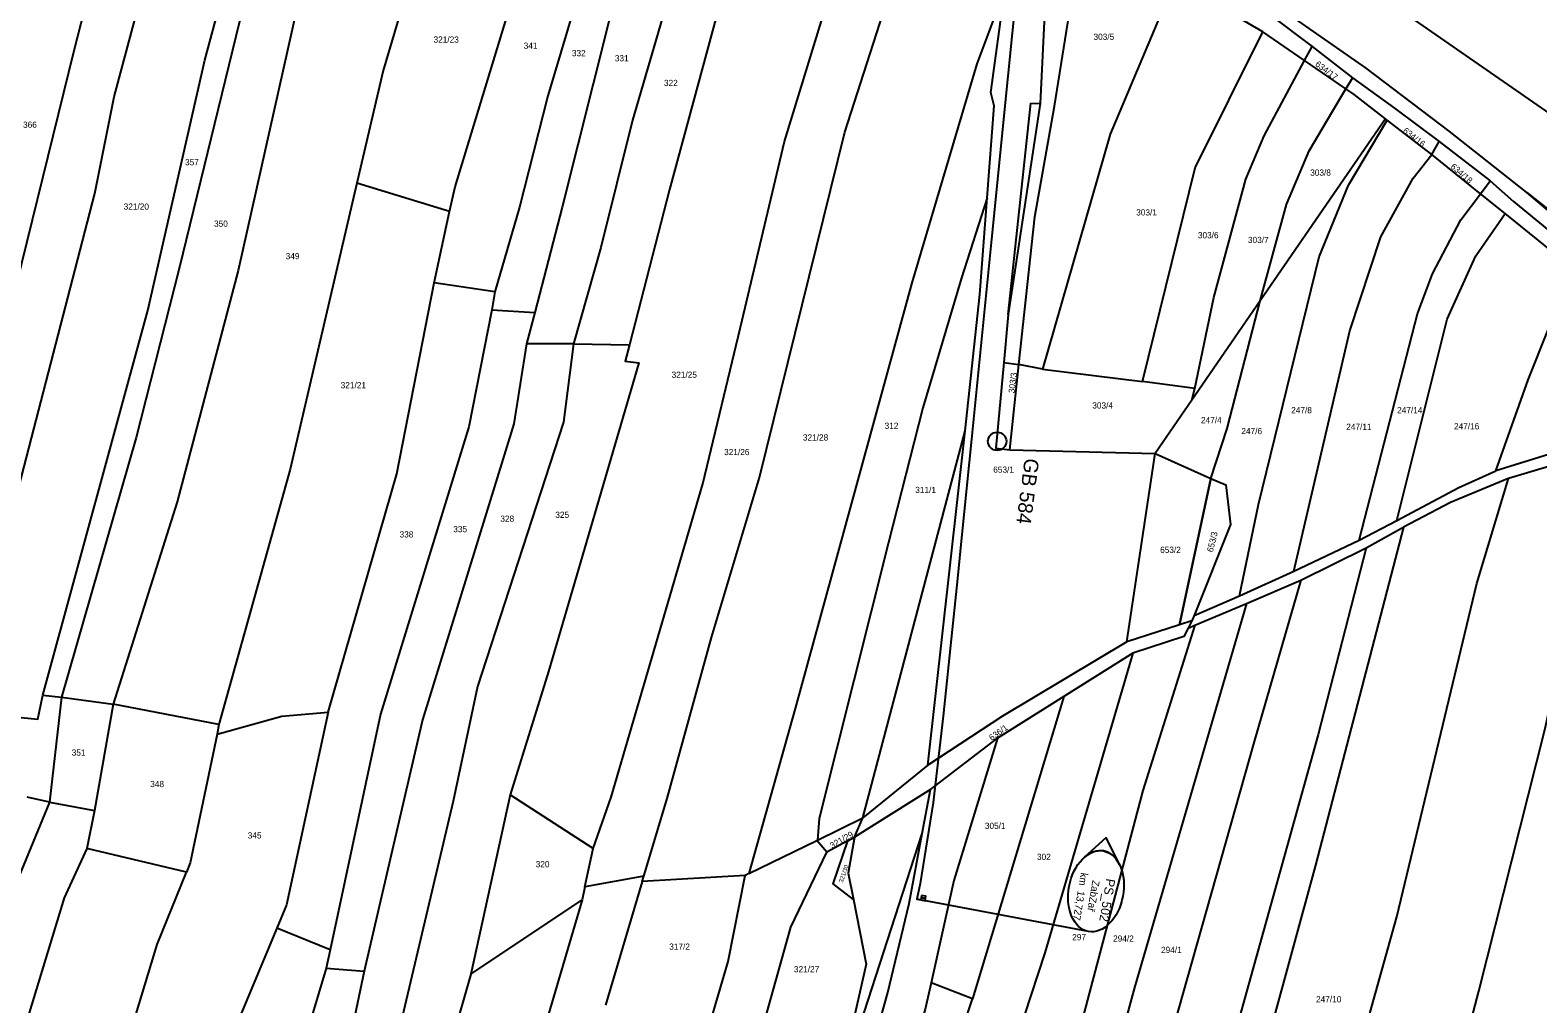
# Model space of a CAD drawing. Extents: x -746176 to -739709, y -1128407 to -1124482.
# Drawn here: x -743602.7 to -743188.7, y -1127823.5 to -1127556.1 of the extents above; entities that cross this region are included whole.
import ezdxf

# ---------------------------------------------------------------- set-up
doc = ezdxf.new("R2010")
doc.units = 0
for name, color, linetype in [('_Násyp', 7, 'Continuous'), ('_Zabezpečovací zařízení', 7, 'Continuous'), ('_Zabezpečovací zařízení_trasa', 7, 'Continuous'), ('bublina_růžová_230_čára_tenká', 7, 'Continuous'), ('bublina_růžová_230_čára_tučná', 7, 'Continuous'), ('Hranice parcel', 7, 'Continuous'), ('Parcelní čísla', 7, 'Continuous'), ('Vnitřní kresba', 7, 'Continuous'), ('Vrstva 53', 7, 'Continuous'), ('ŽBP', 7, 'Continuous')]:
    doc.layers.add(name, color=color, linetype=linetype)

msp = doc.modelspace()

# ---------------------------------------------------------------- linework, layer by layer
at = {"layer": '_Zabezpečovací zařízení'}
for p, q in [((-743357.94, -1127793.74), (-743358.15, -1127794.97)), ((-743358.15, -1127794.97), (-743356.92, -1127795.19)), ((-743356.81, -1127794.57), (-743358.04, -1127794.36)), ((-743356.71, -1127793.96), (-743357.94, -1127793.74)), ((-743356.92, -1127795.19), (-743356.71, -1127793.96))]:
    msp.add_line(p, q, dxfattribs=at)
msp.add_lwpolyline([(-743357.94, -1127793.74), (-743358.04, -1127794.36), (-743356.81, -1127794.57), (-743356.71, -1127793.96), (-743357.94, -1127793.74)], dxfattribs=at)
at = {"layer": '_Zabezpečovací zařízení_trasa'}
msp.add_lwpolyline([(-743301.12, -1127329.13), (-743306.79, -1127349.51), (-743311.54, -1127370.06), (-743315.69, -1127392.87), (-743318.79, -1127415.84), (-743321.57, -1127442.6), (-743324.27, -1127469.35), (-743329.51, -1127521.46), (-743334.23, -1127568.82), (-743338.71, -1127613.56), (-743341.47, -1127641), (-743342.85, -1127654.73), (-743344.22, -1127668.45), (-743346.84, -1127694.61), (-743348.17, -1127707.68), (-743349.5, -1127720.75), (-743351.96, -1127744.53), (-743354.76, -1127768.22), (-743358.32, -1127790.48), (-743359.2, -1127794.79), (-743358.15, -1127794.97)], dxfattribs=at)
at = {"layer": 'bublina_růžová_230_čára_tenká'}
msp.add_line((-743312.1, -1127803.66), (-743359.2, -1127794.79), dxfattribs=at)
at = {"layer": 'bublina_růžová_230_čára_tučná'}
for p, q in [((-743307.25, -1127777.86), (-743313.36, -1127783.41)), ((-743307.25, -1127777.86), (-743313.36, -1127783.41)), ((-743303.57, -1127785.25), (-743307.25, -1127777.86)), ((-743303.57, -1127785.25), (-743307.25, -1127777.86))]:
    msp.add_line(p, q, dxfattribs=at)
msp.add_ellipse((-743310.02, -1127792.6), major_axis=(-2.08, -11.06), ratio=0.666667, dxfattribs=at)
msp.add_ellipse((-743310.02, -1127792.6), major_axis=(2.08, 11.06), ratio=0.666473, start_param=5.557317, end_param=7.009053, dxfattribs=at)
at = {"layer": 'Hranice parcel'}
for p, q in [((-743264.18, -1127556.62), (-743288.35, -1127542.49)), ((-743252.73, -1127564.48), (-743264.18, -1127556.62)), ((-743252.73, -1127564.48), (-743250.66, -1127560.62)), ((-743250.66, -1127560.62), (-743239.62, -1127569.19)), ((-743241.42, -1127572.24), (-743252.73, -1127564.48)), ((-743239.62, -1127569.19), (-743241.42, -1127572.24)), ((-743230.52, -1127580.51), (-743264.95, -1127630.5)), ((-743230.04, -1127580.88), (-743230.52, -1127580.51)), ((-743217.78, -1127590.26), (-743230.04, -1127580.88)), ((-743217.78, -1127590.26), (-743215.78, -1127586.74)), ((-743204.41, -1127601.05), (-743217.78, -1127590.26)), ((-743215.78, -1127586.74), (-743201.77, -1127597.55)), ((-743487.51, -1127605.98), (-743512.98, -1127598.18)), ((-743204.41, -1127601.05), (-743201.77, -1127597.55)), ((-743197.68, -1127606.48), (-743204.41, -1127601.05)), ((-743491.75, -1127625.57), (-743487.51, -1127605.98)), ((-743475.06, -1127627.97), (-743491.75, -1127625.57)), ((-743475.06, -1127627.97), (-743475.93, -1127632.96)), ((-743264.95, -1127630.5), (-743283.69, -1127657.72)), ((-743475.93, -1127632.96), (-743464.14, -1127633.66)), ((-743464.14, -1127633.66), (-743466.39, -1127642.3)), ((-743453.46, -1127642.28), (-743466.39, -1127642.3)), ((-743453.46, -1127642.28), (-743438.1, -1127642.54)), ((-743335.37, -1127647.41), (-743331.17, -1127647.95)), ((-743333.67, -1127671.36), (-743331.17, -1127647.95)), ((-743324.73, -1127649.24), (-743331.17, -1127647.95)), ((-743324.73, -1127649.24), (-743297.22, -1127652.59)), ((-743282.86, -1127654.54), (-743297.22, -1127652.59)), ((-743283.69, -1127657.72), (-743282.86, -1127654.54)), ((-743283.69, -1127657.72), (-743293.8, -1127672.4)), ((-743333.67, -1127671.36), (-743293.8, -1127672.4)), ((-743301.55, -1127724.14), (-743293.8, -1127672.4)), ((-743293.8, -1127672.4), (-743278.45, -1127679.23)), ((-743165.44, -1127669.87), (-743196.8, -1127679.29)), ((-743287.1, -1127719.44), (-743278.45, -1127679.23)), ((-743237.76, -1127696.22), (-743227.38, -1127690.77)), ((-743255.66, -1127704.74), (-743237.76, -1127696.22)), ((-743253.81, -1127707.15), (-743235.82, -1127698.28)), ((-743270.64, -1127711.51), (-743255.66, -1127704.74)), ((-743268.66, -1127713.55), (-743253.81, -1127707.15)), ((-743283.11, -1127716.84), (-743270.64, -1127711.51)), ((-743282.88, -1127719.56), (-743268.66, -1127713.55)), ((-743283.71, -1127718.34), (-743287.1, -1127719.44)), ((-743283.71, -1127718.34), (-743284.74, -1127720.35)), ((-743283.11, -1127716.84), (-743283.71, -1127718.34)), ((-743287.1, -1127719.44), (-743301.55, -1127724.14)), ((-743284.74, -1127720.35), (-743282.88, -1127719.56)), ((-743299.93, -1127727.23), (-743318.89, -1127739.14)), ((-743599.16, -1127738.75), (-743594.04, -1127739.28)), ((-743594.04, -1127739.28), (-743597.33, -1127768.16)), ((-743594.04, -1127739.28), (-743579.85, -1127741.23)), ((-743318.89, -1127739.14), (-743343.93, -1127822.1)), ((-743318.89, -1127739.14), (-743337.1, -1127750.58)), ((-743579.85, -1127741.23), (-743585.04, -1127770.39)), ((-743550.89, -1127746.78), (-743579.85, -1127741.23)), ((-743550.89, -1127746.78), (-743551.29, -1127749.44)), ((-743355.5, -1127764.66), (-743337.1, -1127750.58)), ((-743597.33, -1127768.16), (-743603.54, -1127766.74)), ((-743597.33, -1127768.16), (-743585.04, -1127770.39)), ((-743470.88, -1127766.12), (-743481.69, -1127815.4)), ((-743448.1, -1127780.84), (-743470.88, -1127766.12)), ((-743355.5, -1127764.66), (-743376.33, -1127777.73)), ((-743357.75, -1127776.76), (-743355.5, -1127764.66)), ((-743585.04, -1127770.39), (-743587.1, -1127780.87)), ((-743386.45, -1127778.59), (-743374.07, -1127772.46)), ((-743376.33, -1127777.73), (-743374.07, -1127772.46)), ((-743405.3, -1127787.74), (-743386.64, -1127778.68)), ((-743386.64, -1127778.68), (-743386.45, -1127778.59)), ((-743383.94, -1127781.89), (-743386.64, -1127778.68)), ((-743378.18, -1127778.74), (-743383.94, -1127781.89)), ((-743378.18, -1127778.74), (-743376.33, -1127777.73)), ((-743559.77, -1127787.4), (-743587.1, -1127780.87)), ((-743450.34, -1127791.41), (-743448.1, -1127780.84)), ((-743434.17, -1127788.45), (-743450.34, -1127791.41)), ((-743406.34, -1127788.25), (-743434.62, -1127789.95)), ((-743434.62, -1127789.95), (-743434.17, -1127788.45)), ((-743405.3, -1127787.74), (-743406.34, -1127788.25)), ((-743450.34, -1127791.41), (-743451.09, -1127794.94)), ((-743434.62, -1127789.95), (-743444.74, -1127823.92)), ((-743481.69, -1127815.4), (-743451.09, -1127794.94)), ((-743520.33, -1127808.71), (-743534.94, -1127802.78)), ((-743520.33, -1127808.71), (-743521.42, -1127813.7)), ((-743521.42, -1127813.7), (-743511, -1127814.57)), ((-743511, -1127814.57), (-743513.93, -1127828.42)), ((-743481.69, -1127815.4), (-743490.01, -1127844.27)), ((-743343.93, -1127822.1), (-743355.31, -1127817.79)), ((-743351.87, -1127846.33), (-743343.93, -1127822.1))]:
    msp.add_line(p, q, dxfattribs=at)
for points in [[(-743551.54, -1127422.32), (-743561.28, -1127447), (-743590.72, -1127561.84), (-743612.33, -1127649.25), (-743636.86, -1127737.44)], [(-743621.23, -1127735.75), (-743612.44, -1127707.12), (-743584.91, -1127601.01), (-743579.58, -1127574.43), (-743546.31, -1127450.09), (-743538.8, -1127430.57)], [(-743599.16, -1127738.75), (-743570.37, -1127633.12), (-743554.73, -1127564.38), (-743526.58, -1127459.91), (-743519.14, -1127443.31)], [(-743514.57, -1127446.27), (-743521.89, -1127463.56), (-743545.21, -1127553.77), (-743561.74, -1127621.6), (-743573.61, -1127667.99), (-743594.04, -1127739.28)], [(-743498.56, -1127456.64), (-743508.94, -1127484.15), (-743529.52, -1127550.64), (-743545.56, -1127622.11), (-743562.33, -1127685.66), (-743579.85, -1127741.23)], [(-743474.35, -1127470.68), (-743486.04, -1127500.8), (-743505.77, -1127567.21), (-743512.98, -1127598.18)], [(-743487.51, -1127605.98), (-743486.02, -1127599.12), (-743462.28, -1127521.15), (-743455.14, -1127498.91), (-743448.36, -1127479.77)], [(-743431.85, -1127485.54), (-743442.53, -1127513.63), (-743460.53, -1127574.17), (-743468.34, -1127604.77), (-743475.06, -1127627.97)], [(-743421.29, -1127489.23), (-743434.5, -1127524.7), (-743443.83, -1127553.78), (-743456.63, -1127604.77), (-743464.14, -1127633.66)], [(-743409.64, -1127493.62), (-743419.11, -1127518.4), (-743437.32, -1127580.9), (-743446, -1127615.82), (-743453.46, -1127642.28)], [(-743394.17, -1127499.58), (-743406.86, -1127530.38), (-743414.11, -1127551.95), (-743427.12, -1127599.89), (-743438.1, -1127642.54)], [(-743448.1, -1127780.84), (-743443.18, -1127766.73), (-743418.02, -1127680.71), (-743407.6, -1127637.74), (-743395.56, -1127586.74), (-743381.16, -1127539.8), (-743369.67, -1127509.02)], [(-743434.17, -1127788.45), (-743427.78, -1127767.16), (-743415.63, -1127722.89), (-743402.41, -1127679.01), (-743378.99, -1127584.19), (-743364.14, -1127538.04), (-743355.14, -1127514.62)], [(-743314.91, -1127527.24), (-743320.68, -1127537.21), (-743321.34, -1127538.34), (-743323.67, -1127542.37), (-743325.37, -1127576.31), (-743334.16, -1127634.18), (-743335.37, -1127647.41)], [(-743314.71, -1127527.98), (-743288.02, -1127539.72), (-743267.92, -1127547.88), (-743262.15, -1127552), (-743250.66, -1127560.62)], [(-743331.17, -1127647.95), (-743326.84, -1127607.36), (-743321.41, -1127576.97), (-743314.01, -1127530.6)], [(-743110.84, -1127632.34), (-743140.32, -1127610.37), (-743254.82, -1127530.84)], [(-743288.35, -1127542.49), (-743306.14, -1127584.68), (-743324.73, -1127649.24)], [(-743339.88, -1127602.23), (-743337.94, -1127576.95), (-743338.86, -1127573.29), (-743335.16, -1127545.74)], [(-743191.76, -1127600.69), (-743213.04, -1127583.89), (-743235.8, -1127566.59), (-743259.6, -1127550), (-743265.25, -1127546.83)], [(-743337.56, -1127551.48), (-743342.72, -1127565.43), (-743360.58, -1127625.49), (-743392.64, -1127742.44), (-743405.3, -1127787.74)], [(-743297.22, -1127652.59), (-743282.79, -1127593.92), (-743264.18, -1127556.62)], [(-743282.86, -1127654.54), (-743277.65, -1127629.53), (-743268.85, -1127597.04), (-743263.84, -1127585.18), (-743252.73, -1127564.48)], [(-743239.62, -1127569.19), (-743228.08, -1127577.6), (-743215.78, -1127586.74)], [(-743264.95, -1127630.5), (-743257.74, -1127603.98), (-743251.48, -1127589.3), (-743241.42, -1127572.24)], [(-743230.52, -1127580.51), (-743239.1, -1127573.83), (-743241.42, -1127572.24)], [(-743270.64, -1127711.51), (-743265.43, -1127686.37), (-743248.78, -1127618.41), (-743240.66, -1127598.71), (-743230.04, -1127580.88)], [(-743255.66, -1127704.74), (-743240.36, -1127638.68), (-743231.77, -1127612.89), (-743222.92, -1127596.81), (-743217.78, -1127590.26)], [(-743512.98, -1127598.18), (-743531.28, -1127676.73), (-743550.89, -1127746.78)], [(-743201.77, -1127597.55), (-743195.41, -1127603.21), (-743175.98, -1127619.13)], [(-743339.88, -1127602.23), (-743346.97, -1127624.14), (-743357.58, -1127659.83), (-743366.95, -1127696.84), (-743386.06, -1127772.64), (-743386.45, -1127778.59)], [(-743374.07, -1127772.46), (-743345.92, -1127666.2), (-743341.91, -1127628.76), (-743339.88, -1127602.23)], [(-743237.76, -1127696.22), (-743221.74, -1127634), (-743217.66, -1127623.08), (-743209.85, -1127608.23), (-743204.41, -1127601.05)], [(-743119.31, -1127660.83), (-743131.7, -1127652.73), (-743150.41, -1127635.6), (-743191.76, -1127600.69)], [(-743191.76, -1127600.69), (-743179.42, -1127610.43), (-743144.82, -1127637.7), (-743125.82, -1127655.26)], [(-743227.38, -1127690.77), (-743213.64, -1127635.49), (-743205.71, -1127618.08), (-743197.68, -1127606.48)], [(-743177.68, -1127622.43), (-743184.29, -1127617.28), (-743197.68, -1127606.48)], [(-743200.21, -1127677.12), (-743191.34, -1127652.2), (-743185.76, -1127638.12), (-743177.68, -1127622.43)], [(-743520.82, -1127743.45), (-743502.02, -1127678), (-743491.75, -1127625.57)], [(-743278.45, -1127679.23), (-743274.02, -1127665.56), (-743264.95, -1127630.5)], [(-743475.93, -1127632.96), (-743482.22, -1127665.09), (-743506.51, -1127743.94), (-743520.33, -1127808.71)], [(-743466.39, -1127642.3), (-743469.86, -1127664.22), (-743494.95, -1127745.55), (-743511, -1127814.57)], [(-743453.46, -1127642.28), (-743456.19, -1127663.78), (-743479.83, -1127736.34), (-743486.56, -1127767.82), (-743500.98, -1127829.09)], [(-743438.1, -1127642.54), (-743439.27, -1127647.07), (-743435.59, -1127647.51), (-743460.31, -1127732.22), (-743470.88, -1127766.12)], [(-743335.37, -1127647.41), (-743337.51, -1127670.9), (-743333.67, -1127671.36)], [(-743170.99, -1127668.05), (-743171.32, -1127668.14), (-743200.21, -1127677.12)], [(-743237.87, -1127943.87), (-743228.87, -1127911.59), (-743204.89, -1127820), (-743186.75, -1127748.28), (-743176.72, -1127702.48), (-743165.44, -1127669.87)], [(-743227.38, -1127690.77), (-743210.43, -1127681.71), (-743200.21, -1127677.12)], [(-743278.45, -1127679.23), (-743274.37, -1127681.04), (-743273.1, -1127691.93), (-743283.11, -1127716.84)], [(-743264.74, -1127937.21), (-743244.37, -1127860.25), (-743227.42, -1127799.64), (-743205.44, -1127708.1), (-743196.8, -1127679.29)], [(-743196.8, -1127679.29), (-743197.04, -1127679.36), (-743212.68, -1127685.82), (-743225.59, -1127692.63)], [(-743225.59, -1127692.63), (-743249.75, -1127785.46), (-743287.33, -1127923.2), (-743297.04, -1127954.42)], [(-743235.82, -1127698.28), (-743226.1, -1127692.9), (-743225.59, -1127692.63)], [(-743235.82, -1127698.28), (-743249, -1127749.54), (-743300.05, -1127932.95), (-743303.92, -1127943.26)], [(-743253.81, -1127707.15), (-743266.62, -1127751.47), (-743299.27, -1127867.01), (-743314.24, -1127914.43)], [(-743268.66, -1127713.55), (-743299.42, -1127819.01), (-743313.64, -1127871.22), (-743325.19, -1127907.9)], [(-743282.88, -1127719.56), (-743297.14, -1127764.91), (-743314.44, -1127830.42), (-743327.83, -1127872.04)], [(-743284.74, -1127720.35), (-743285.9, -1127722.61), (-743299.93, -1127727.23)], [(-743301.55, -1127724.14), (-743335.67, -1127744.51), (-743356.23, -1127757.98), (-743374.07, -1127772.46)], [(-743299.93, -1127727.23), (-743324.05, -1127809.53), (-743337.26, -1127849.72)], [(-743623.51, -1127743.05), (-743600.59, -1127745.39), (-743599.16, -1127738.75)], [(-743551.29, -1127749.44), (-743533.58, -1127744.49), (-743520.82, -1127743.45)], [(-743520.82, -1127743.45), (-743532.26, -1127796.34), (-743534.94, -1127802.78)], [(-743551.29, -1127749.44), (-743558.72, -1127784.83), (-743559.77, -1127787.4)], [(-743337.1, -1127750.58), (-743349.06, -1127789.63), (-743355.31, -1127817.79)], [(-743597.33, -1127768.16), (-743606.36, -1127789.97), (-743626.72, -1127859.49), (-743638.35, -1127905.26), (-743659.84, -1127983.12)], [(-743388.31, -1127884.17), (-743374.7, -1127829.05), (-743357.75, -1127776.76)], [(-743388.31, -1127884.17), (-743381.41, -1127866.19), (-743374.06, -1127845.14), (-743367.18, -1127820.36), (-743361.33, -1127795.97), (-743357.75, -1127776.76)], [(-743376.61, -1127794.9), (-743382.22, -1127790.53), (-743378.18, -1127778.74)], [(-743376.33, -1127777.73), (-743378.06, -1127787.61), (-743376.61, -1127794.9)], [(-743587.1, -1127780.87), (-743593.35, -1127794.42), (-743608.73, -1127844.98), (-743637.18, -1127949.14), (-743646.98, -1127982.69)], [(-743440.39, -1127970.17), (-743422.4, -1127904.63), (-743393.77, -1127802.48), (-743383.94, -1127781.89)], [(-743573.69, -1127826.51), (-743567.83, -1127807.19), (-743559.77, -1127787.4)], [(-743416.75, -1127831.61), (-743411.02, -1127811.93), (-743406.34, -1127788.25)], [(-743451.09, -1127794.94), (-743476.79, -1127882.29), (-743506.61, -1128001.51)], [(-743376.61, -1127794.9), (-743373.1, -1127812.6), (-743383.25, -1127857.46), (-743405.64, -1127911.7), (-743425.47, -1127948.11), (-743440.39, -1127970.17)], [(-743534.94, -1127802.78), (-743547.45, -1127832.8), (-743549.4, -1127840.4)], [(-743521.42, -1127813.7), (-743536.99, -1127865.85), (-743543.84, -1127893.3), (-743572.96, -1128001.22)], [(-743355.31, -1127817.79), (-743356.91, -1127824.97), (-743366.89, -1127859.22), (-743379.33, -1127892.58), (-743393.74, -1127924.28), (-743408.65, -1127951.21)]]:
    msp.add_lwpolyline(points, dxfattribs=at)
at = {"layer": 'Vnitřní kresba'}
for p, q in [((-743334.16, -1127634.18), (-743327.93, -1127576.22)), ((-743327.93, -1127576.22), (-743325.37, -1127576.31)), ((-743356.23, -1127757.98), (-743345.92, -1127666.2))]:
    msp.add_line(p, q, dxfattribs=at)
at = {"layer": 'Vrstva 53'}
for points in [[(-743332.17, -1127523.47), (-743323.8, -1127523.97), (-743314.91, -1127527.24), (-743323.67, -1127542.37), (-743325.37, -1127576.31), (-743334.16, -1127634.18), (-743335.37, -1127647.41), (-743337.51, -1127670.9), (-743333.67, -1127671.36), (-743293.8, -1127672.4), (-743278.45, -1127679.23), (-743287.1, -1127719.44), (-743301.55, -1127724.14), (-743335.67, -1127744.51), (-743356.23, -1127757.98), (-743374.07, -1127772.46), (-743345.92, -1127666.2), (-743341.91, -1127628.76), (-743339.88, -1127602.23), (-743337.94, -1127576.95), (-743338.86, -1127573.29), (-743335.16, -1127545.74), (-743332.17, -1127523.47)], [(-743367.18, -1127820.36), (-743361.33, -1127795.97), (-743357.75, -1127776.76), (-743355.5, -1127764.66), (-743337.1, -1127750.58), (-743349.06, -1127789.63), (-743355.31, -1127817.79)]]:
    msp.add_lwpolyline(points, dxfattribs=at)
at = {"layer": 'ŽBP'}
msp.add_circle((-743337.16, -1127669.05), 2.52, dxfattribs=at)

# ---------------------------------------------------------------- texts
at = {"layer": '_Násyp'}
for s, height, p in [('km  13,727', 2, (-743314.18, -1127787.38)), ('ZabZař', 2, (-743310.98, -1127789.49)), ('PS_502', 2.5, (-743307.17, -1127789))]:
    msp.add_text(s, height=height, rotation=260.5528, dxfattribs=at).set_placement(p)
at = {"layer": 'Parcelní čísla'}
for s, p in [('303/5', (-743310.71, -1127558.81)), ('321/23', (-743491.92, -1127559.57)), ('341', (-743467.17, -1127561.25)), ('332', (-743453.93, -1127563.29)), ('331', (-743442.14, -1127564.69)), ('322', (-743428.65, -1127571.49)), ('366', (-743604.63, -1127582.95)), ('357', (-743560.15, -1127593.26)), ('303/8', (-743251.21, -1127596.1)), ('321/20', (-743577.01, -1127605.44)), ('303/1', (-743298.98, -1127607.03)), ('350', (-743552.19, -1127610.13)), ('303/6', (-743282.05, -1127613.3)), ('303/7', (-743268.3, -1127614.6)), ('349', (-743532.52, -1127619.03)), ('321/25', (-743426.55, -1127651.61)), ('321/21', (-743517.42, -1127654.48)), ('303/4', (-743311.04, -1127660.04)), ('247/8', (-743256.43, -1127661.34)), ('247/14', (-743227.34, -1127661.34)), ('312', (-743368.06, -1127665.63)), ('247/4', (-743281.19, -1127664.08)), ('247/11', (-743241.31, -1127665.91)), ('247/16', (-743211.72, -1127665.77)), ('321/28', (-743390.5, -1127668.83)), ('247/6', (-743270.11, -1127667.08)), ('321/26', (-743412.13, -1127672.84)), ('653/1', (-743338.24, -1127677.68)), ('311/1', (-743359.65, -1127683.25)), ('328', (-743473.57, -1127691.14)), ('325', (-743458.48, -1127690.06)), ('338', (-743501.25, -1127695.45)), ('335', (-743486.51, -1127694.01)), ('653/2', (-743292.41, -1127699.7)), ('351', (-743591.27, -1127755.37)), ('348', (-743569.71, -1127764)), ('345', (-743542.94, -1127778.11)), ('305/1', (-743340.54, -1127775.48)), ('320', (-743463.87, -1127786.02)), ('302', (-743326.22, -1127783.99)), ('297', (-743316.55, -1127806.06)), ('294/2', (-743305.33, -1127806.45)), ('317/2', (-743427.21, -1127808.66)), ('294/1', (-743292.17, -1127809.55)), ('321/27', (-743392.96, -1127814.86)), ('247/10', (-743249.61, -1127823.1))]:
    msp.add_text(s, height=1.7, dxfattribs=at).set_placement(p)
for s, height, rotation, p in [('634/17', 1.7, 323, (-743249.99, -1127565.8)), ('634/16', 1.7, 322, (-743225.92, -1127584.07)), ('634/18', 1.7, 319, (-743212.8, -1127593.85)), ('303/3', 1.7, 83, (-743332.39, -1127655.92)), ('653/3', 1.7, 76, (-743277.95, -1127699.61)), ('636/1', 1.7, 36, (-743338.64, -1127751.38)), ('321/29', 1.7, 30, (-743382.47, -1127780.96)), ('321/30', 1.19, 71, (-743379.55, -1127790.35))]:
    msp.add_text(s, height=height, rotation=rotation, dxfattribs=at).set_placement(p)
at = {"layer": 'ŽBP'}
msp.add_text('GB 584', height=4, rotation=262.5779, dxfattribs=at).set_placement((-743329.58, -1127673.54))

doc.saveas('drawing.dxf')
